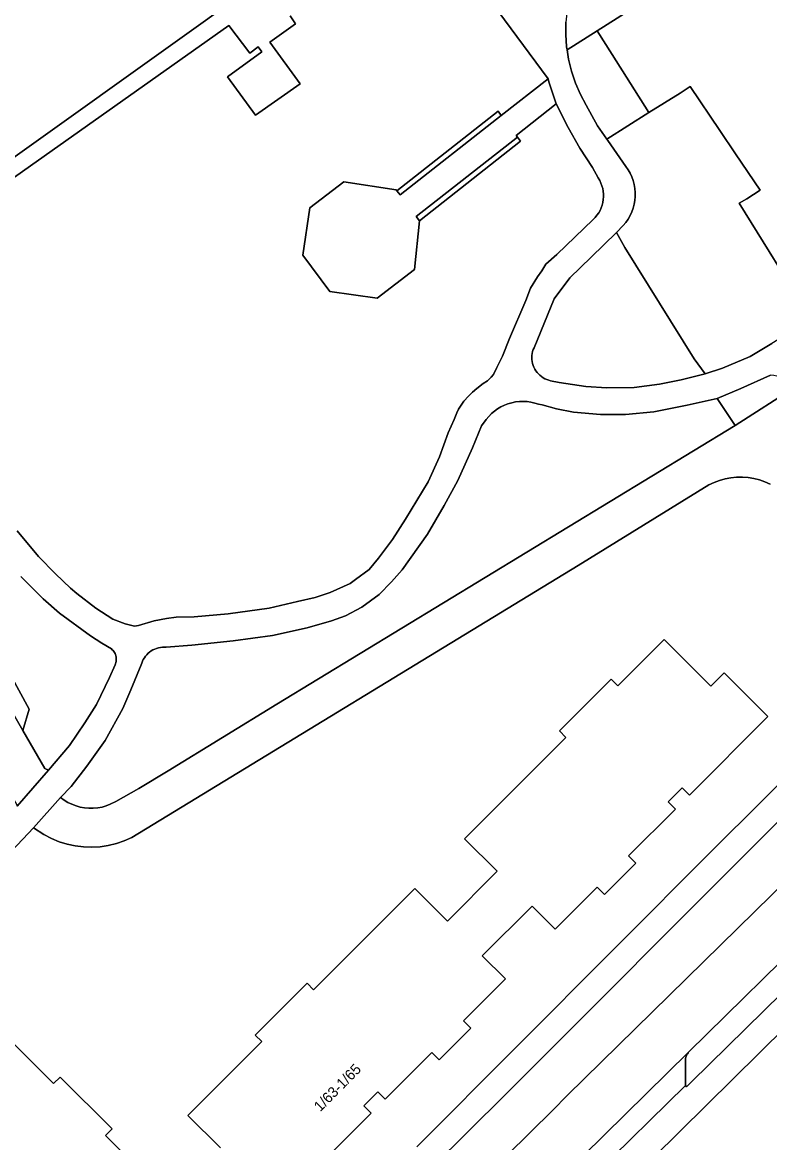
# Model space of a CAD drawing. Extents: x 162788 to 163838, y 385791 to 386523.
# Drawn here: x 163072 to 163143.1, y 386105.3 to 386211.9 of the extents above; entities that cross this region are included whole.
import ezdxf

# ---------------------------------------------------------------- set-up
doc = ezdxf.new("R2010")
doc.units = 0
for name, color, linetype in [('IMGEO_Berm_groen', 7, 'Continuous'), ('IMGEO_Erf', 7, 'Continuous'), ('IMGEO_Groenvoorziening', 7, 'Continuous'), ('IMGEO_Pand', 7, 'Continuous'), ('IMGEO_Pand_nummerreeks', 7, 'Continuous'), ('IMGEO_Parkeervlak_open', 7, 'Continuous'), ('IMGEO_Voetpad_open', 7, 'Continuous'), ('IMGEO_Woonerf_gesloten', 7, 'Continuous'), ('IMGEO_Woonerf_open', 7, 'Continuous')]:
    doc.layers.add(name, color=color, linetype=linetype)

msp = doc.modelspace()

# ---------------------------------------------------------------- linework, layer by layer
at = {"layer": 'IMGEO_Berm_groen'}
for points in [[(163156.62, 386148.64), (163142.94, 386134.85), (163117.96, 386109.83), (163097.04, 386089.07)], [(163102.96, 386089.09), (163122.49, 386108.37), (163123.87, 386109.74), (163156.29, 386141.59)], [(163160.09, 386138.11), (163135.42, 386113.88), (163135.36, 386113.81), (163135.3, 386113.73), (163135.25, 386113.65), (163135.21, 386113.57), (163135.17, 386113.48), (163135.14, 386113.39), (163135.12, 386113.29), (163135.12, 386110.69), (163135.22, 386110.58), (163135.7, 386111.04), (163166.6, 386141.42)]]:
    msp.add_lwpolyline(points, dxfattribs=at)
at = {"layer": 'IMGEO_Erf'}
msp.add_lwpolyline([(163158.27, 386231.02), (163155.82, 386235.03), (163136.27, 386225.97), (163132.74, 386224.35), (163130.49, 386223.11), (163129.8, 386222.6), (163128.43, 386221.27), (163127.43, 386220.24), (163126.53, 386219.13), (163125.72, 386217.95), (163125.01, 386216.7), (163124.41, 386215.4), (163124.09, 386214.26), (163123.87, 386213.1), (163123.75, 386211.92), (163123.73, 386210.74), (163123.81, 386209.56), (163123.86, 386209.28), (163126.72, 386211.09), (163130.88, 386213.71)], close=True, dxfattribs=at)
for points in [[(163053.39, 386193.12), (163054.82, 386191.67), (163058.03, 386187.75), (163058.05, 386187.72), (163059.18, 386188.5), (163060.22, 386187.16), (163063.6, 386189.54), (163061.56, 386192.21), (163063.86, 386193.8), (163094.9, 386216.01), (163096.44, 386213.92), (163109.74, 386223.18)], [(163143.18, 386167.94), (163142.67, 386168.17), (163142.15, 386168.35), (163141.62, 386168.49), (163141.08, 386168.58), (163140.53, 386168.61), (163139.98, 386168.61), (163139.43, 386168.55), (163138.89, 386168.45), (163138.36, 386168.29), (163137.85, 386168.1), (163137.35, 386167.86), (163124.9, 386160.21), (163082.45, 386134.32), (163081.73, 386133.99), (163080.98, 386133.73), (163080.21, 386133.55), (163079.42, 386133.43), (163078.63, 386133.38), (163077.84, 386133.41), (163077.05, 386133.5), (163076.28, 386133.67), (163075.52, 386133.91), (163074.79, 386134.21), (163074.09, 386134.58), (163073.09, 386135.24), (163062.74, 386124.27)], [(163090.89, 386104.76), (163087.79, 386107.86), (163094.81, 386114.88), (163094.19, 386115.5), (163099.12, 386120.43), (163099.74, 386119.81), (163109.38, 386129.45), (163112.48, 386126.35), (163117.21, 386131.09), (163114.11, 386134.18), (163123.75, 386143.82), (163123.13, 386144.45), (163128.06, 386149.38), (163128.68, 386148.76), (163133.09, 386153.16), (163137.54, 386148.71), (163138.81, 386149.98), (163142.96, 386145.82), (163135.49, 386138.35), (163134.8, 386139.04), (163133.47, 386137.71), (163134.16, 386137.02), (163129.71, 386132.57), (163130.41, 386131.87), (163127.41, 386128.87), (163126.71, 386129.57), (163122.72, 386125.58), (163120.52, 386127.78), (163115.79, 386123.04), (163117.99, 386120.85), (163114, 386116.86), (163114.7, 386116.16), (163111.7, 386113.16), (163111, 386113.85), (163106.55, 386109.4), (163105.86, 386110.09), (163104.53, 386108.77), (163105.22, 386108.08), (163097.75, 386100.6)], [(163109.57, 386104.88), (163137.82, 386133.23), (163155.34, 386150.64)], [(163144.69, 386116.33), (163116.89, 386088.83), (163094.14, 386066.38), (163090.23, 386062.55), (163093.08, 386059.67), (163106.35, 386045.61), (163117.91, 386034.05), (163120.62, 386031.36)], [(163068.21, 386100.47), (163060.74, 386107.94), (163064.89, 386112.09), (163066.15, 386110.83), (163070.61, 386115.28), (163075.01, 386110.88), (163075.64, 386111.5), (163080.57, 386106.57), (163079.95, 386105.95), (163086.01, 386099.88)]]:
    msp.add_lwpolyline(points, dxfattribs=at)
at = {"layer": 'IMGEO_Groenvoorziening'}
for points in [[(163071.54, 386163.51), (163073.56, 386161.05), (163075.18, 386159.4), (163076.62, 386158.04), (163077.2, 386157.52), (163079.02, 386156.14), (163080.64, 386155.08), (163081.8, 386154.63), (163082.69, 386154.41), (163083.07, 386154.49), (163084.57, 386154.93), (163085.75, 386155.14), (163086.66, 386155.28), (163088.39, 386155.32), (163091.61, 386155.59), (163095.5, 386156.15), (163098.2, 386156.77), (163099.9, 386157.14), (163101.31, 386157.62), (163103.23, 386158.49), (163103.72, 386158.86), (163105.02, 386159.82), (163105.9, 386160.88), (163107.26, 386162.67), (163108.48, 386164.62), (163110.65, 386168.17), (163111.72, 386170.55), (163112.54, 386172.83), (163113.11, 386174.1), (163113.35, 386174.73), (163113.54, 386175.09), (163113.84, 386175.55), (163114.02, 386175.85), (163114.47, 386176.33), (163114.86, 386176.7), (163115.28, 386177.04), (163115.87, 386177.51), (163116.29, 386177.79), (163116.62, 386178.12), (163116.85, 386178.38), (163117.16, 386179.04), (163117.72, 386180.13), (163118.37, 386181.8), (163119.94, 386185.43), (163120.38, 386186.59), (163121.05, 386187.67), (163121.44, 386188.25), (163121.84, 386188.88), (163122.87, 386189.8), (163126.34, 386193.13), (163126.53, 386193.32), (163126.7, 386193.53), (163126.86, 386193.75), (163126.99, 386193.99), (163127.1, 386194.23), (163127.19, 386194.49), (163127.26, 386194.75), (163127.3, 386195.02), (163127.33, 386195.28), (163127.32, 386195.55), (163127.3, 386195.82), (163127.25, 386196.09), (163127.17, 386196.35), (163127.08, 386196.6), (163126.96, 386196.84), (163126.82, 386197.08), (163126.26, 386198.09), (163125.07, 386199.91), (163123.96, 386201.89), (163122.83, 386204.14), (163119.02, 386201.14), (163119.14, 386200.98), (163119.42, 386200.57), (163109.81, 386193.01), (163109.35, 386188.38), (163105.8, 386185.63), (163101.28, 386186.28), (163098.72, 386189.72), (163099.37, 386194.23), (163102.62, 386196.71), (163107.59, 386195.96), (163107.67, 386195.86), (163117.29, 386203.43), (163117.59, 386203.03), (163122.04, 386206.53), (163110.75, 386221.82)], [(163097.5, 386212.51), (163098.02, 386211.76), (163095.56, 386210), (163098.45, 386206.04), (163094.22, 386203.06), (163091.55, 386206.71), (163094.83, 386209.1), (163094.46, 386209.55), (163093.67, 386208.95), (163091.66, 386211.58), (163067.36, 386194.4)], [(163065.54, 386159.58), (163072.69, 386146.51), (163072.09, 386144.5), (163074.17, 386140.87), (163074.53, 386140.72), (163076.51, 386143.08), (163077.98, 386145.21), (163079.09, 386146.97), (163080.31, 386149.54), (163080.85, 386150.74), (163080.89, 386150.84), (163080.93, 386150.95), (163080.95, 386151.06), (163080.96, 386151.17), (163080.97, 386151.28), (163080.96, 386151.39), (163080.95, 386151.5), (163080.92, 386151.61), (163080.89, 386151.72), (163080.85, 386151.82), (163080.8, 386151.92), (163080.74, 386152.01), (163080.67, 386152.1), (163080.59, 386152.18), (163080.51, 386152.26), (163079.58, 386152.81), (163078.51, 386153.5), (163075.55, 386155.66), (163074.02, 386157.02), (163071.9, 386159.16)]]:
    msp.add_lwpolyline(points, dxfattribs=at)
for points in [[(163128.15, 386208.82), (163126.72, 386211.09), (163123.86, 386209.28), (163123.99, 386208.39), (163124.27, 386207.24), (163124.65, 386206.12), (163125.12, 386205.04), (163125.68, 386204), (163126.76, 386202.06), (163127.64, 386200.78), (163131.63, 386203.3)], [(163117.59, 386203.03), (163117.29, 386203.43), (163107.67, 386195.86), (163107.98, 386195.47)], [(163119.14, 386200.98), (163109.51, 386193.41), (163109.81, 386193.01), (163119.42, 386200.57)], [(163128.55, 386191.88), (163126.16, 386189.53), (163124.11, 386187.59), (163122.62, 386185.59), (163120.71, 386180.93), (163120.63, 386180.75), (163120.58, 386180.57), (163120.53, 386180.38), (163120.51, 386180.19), (163120.5, 386179.99), (163120.51, 386179.8), (163120.53, 386179.61), (163120.57, 386179.42), (163120.63, 386179.24), (163120.7, 386179.06), (163120.79, 386178.89), (163120.89, 386178.73), (163121, 386178.57), (163121.13, 386178.43), (163121.27, 386178.3), (163121.42, 386178.18), (163121.58, 386178.07), (163121.75, 386177.98), (163121.93, 386177.9), (163122.11, 386177.84), (163122.29, 386177.79), (163123.1, 386177.61), (163125.63, 386177.23), (163127.65, 386177.12), (163130.25, 386177.15), (163132.65, 386177.47), (163134.71, 386177.86), (163137, 386178.43), (163135.96, 386179.87), (163129.36, 386190.45)], [(163139.83, 386173.53), (163138.14, 386176.08), (163135.28, 386175.46), (163132.12, 386174.82), (163129.41, 386174.56), (163127.04, 386174.57), (163124.47, 386174.8), (163122.86, 386175.11), (163121.47, 386175.48), (163121.13, 386175.55), (163120.78, 386175.66), (163120.42, 386175.74), (163120.05, 386175.8), (163119.68, 386175.82), (163119.32, 386175.81), (163118.95, 386175.77), (163118.59, 386175.69), (163118.23, 386175.59), (163117.89, 386175.46), (163117.56, 386175.29), (163117.24, 386175.1), (163116.94, 386174.89), (163116.66, 386174.65), (163116.41, 386174.38), (163116.17, 386174.1), (163115.72, 386173.49), (163114.87, 386171.39), (163113.47, 386168.28), (163112.16, 386165.91), (163110.57, 386163.17), (163108.16, 386159.77), (163107.15, 386158.64), (163105.97, 386157.44), (163104.33, 386156.22), (163102.78, 386155.42), (163101.45, 386154.94), (163099.12, 386154.28), (163095.84, 386153.54), (163092.09, 386153.03), (163088.17, 386152.63), (163085.72, 386152.41), (163085.54, 386152.42), (163085.35, 386152.42), (163085.16, 386152.4), (163084.98, 386152.36), (163084.8, 386152.31), (163084.62, 386152.24), (163084.46, 386152.16), (163084.29, 386152.07), (163084.14, 386151.96), (163084, 386151.84), (163083.87, 386151.71), (163083.75, 386151.57), (163083.64, 386151.41), (163083.54, 386151.25), (163083.46, 386151.08), (163083.4, 386150.91), (163083.35, 386150.73), (163082.34, 386148.35), (163081.58, 386146.58), (163079.91, 386143.55), (163078.18, 386141.11), (163076.67, 386139.15), (163075.67, 386138.11), (163076.01, 386137.86), (163076.37, 386137.65), (163076.74, 386137.47), (163077.14, 386137.32), (163077.54, 386137.21), (163077.95, 386137.14), (163078.36, 386137.1), (163078.78, 386137.1), (163079.2, 386137.14), (163079.61, 386137.21), (163080.01, 386137.32), (163080.4, 386137.47), (163080.93, 386137.74), (163083.12, 386138.98), (163085.91, 386140.64), (163096.25, 386147)]]:
    msp.add_lwpolyline(points, close=True, dxfattribs=at)
at = {"layer": 'IMGEO_Pand'}
for points in [[(163158.27, 386231.02), (163130.88, 386213.71), (163126.72, 386211.09), (163128.15, 386208.82), (163131.63, 386203.3), (163134.6, 386205.17), (163135.58, 386205.79), (163138.39, 386201.6), (163139.88, 386199.39), (163142.21, 386195.91), (163140.94, 386195.11), (163140.23, 386194.67), (163146.92, 386183.91)], [(163097.75, 386100.6), (163105.22, 386108.08), (163104.53, 386108.77), (163105.86, 386110.09), (163106.55, 386109.4), (163111, 386113.85), (163111.7, 386113.16), (163114.7, 386116.16), (163114, 386116.86), (163117.99, 386120.85), (163115.79, 386123.04), (163120.52, 386127.78), (163122.72, 386125.58), (163126.71, 386129.57), (163127.41, 386128.87), (163130.41, 386131.87), (163129.71, 386132.57), (163134.16, 386137.02), (163133.47, 386137.71), (163134.8, 386139.04), (163135.49, 386138.35), (163142.96, 386145.82), (163138.81, 386149.98), (163137.54, 386148.71), (163133.09, 386153.16), (163128.68, 386148.76), (163128.06, 386149.38), (163123.13, 386144.45), (163123.75, 386143.82), (163114.11, 386134.18), (163117.21, 386131.09), (163112.48, 386126.35), (163109.38, 386129.45), (163099.74, 386119.81), (163099.12, 386120.43), (163094.19, 386115.5), (163094.81, 386114.88), (163087.79, 386107.86), (163090.89, 386104.76)], [(163086.01, 386099.88), (163079.95, 386105.95), (163080.57, 386106.57), (163075.64, 386111.5), (163075.01, 386110.88), (163070.61, 386115.28), (163066.15, 386110.83), (163064.89, 386112.09), (163060.74, 386107.94), (163068.21, 386100.47)]]:
    msp.add_lwpolyline(points, dxfattribs=at)
at = {"layer": 'IMGEO_Parkeervlak_open'}
for points in [[(163063.12, 386160.14), (163072.09, 386144.5), (163072.69, 386146.51), (163065.54, 386159.58)], [(163135.12, 386110.69), (163135.12, 386113.29), (163135.14, 386113.39), (163135.17, 386113.48), (163135.21, 386113.57), (163135.25, 386113.65), (163135.3, 386113.73), (163135.36, 386113.81), (163135.42, 386113.88), (163123.39, 386102.04), (163123.47, 386102.09), (163123.55, 386102.13), (163123.63, 386102.16), (163123.71, 386102.19), (163123.8, 386102.2), (163123.89, 386102.21), (163123.98, 386102.21), (163126.52, 386102.25)]]:
    msp.add_lwpolyline(points, close=True, dxfattribs=at)
at = {"layer": 'IMGEO_Voetpad_open'}
for points in [[(163094.9, 386216.01), (163063.86, 386193.8), (163061.56, 386192.21), (163063.6, 386189.54), (163060.22, 386187.16), (163059.18, 386188.5), (163058.05, 386187.72), (163059, 386186.38), (163059.81, 386184.94), (163066.76, 386190), (163064.81, 386192.51), (163067.36, 386194.4), (163091.66, 386211.58), (163093.67, 386208.95), (163094.46, 386209.55), (163094.83, 386209.1), (163091.55, 386206.71), (163094.22, 386203.06), (163098.45, 386206.04), (163095.56, 386210), (163098.02, 386211.76), (163097.5, 386212.51)], [(163146.92, 386183.91), (163140.23, 386194.67), (163140.94, 386195.11), (163142.21, 386195.91), (163139.88, 386199.39), (163138.39, 386201.6), (163135.58, 386205.79), (163134.6, 386205.17), (163131.63, 386203.3), (163127.64, 386200.78), (163127.74, 386200.64), (163129.44, 386198.18), (163129.66, 386197.87), (163129.85, 386197.54), (163130.01, 386197.2), (163130.14, 386196.84), (163130.24, 386196.47), (163130.3, 386196.09), (163130.33, 386195.71), (163130.33, 386195.33), (163130.3, 386194.95), (163130.24, 386194.58), (163130.14, 386194.21), (163130.01, 386193.85), (163129.85, 386193.51), (163129.65, 386193.17), (163129.43, 386192.86), (163129.19, 386192.57), (163128.55, 386191.88), (163129.36, 386190.45), (163135.96, 386179.87), (163137, 386178.43), (163138.64, 386178.99), (163141.28, 386180.1), (163143.33, 386181.33)]]:
    msp.add_lwpolyline(points, dxfattribs=at)
msp.add_lwpolyline([(163119.14, 386200.98), (163119.02, 386201.14), (163122.83, 386204.14), (163122.15, 386206.14), (163122.12, 386206.23), (163122.04, 386206.53), (163117.59, 386203.03), (163107.98, 386195.47), (163107.67, 386195.86), (163107.59, 386195.96), (163102.62, 386196.71), (163099.37, 386194.23), (163098.72, 386189.72), (163101.28, 386186.28), (163105.8, 386185.63), (163109.35, 386188.38), (163109.81, 386193.01), (163109.51, 386193.41)], close=True, dxfattribs=at)
at = {"layer": 'IMGEO_Woonerf_gesloten'}
for points in [[(163110.75, 386221.82), (163122.04, 386206.53), (163122.12, 386206.23), (163122.15, 386206.14), (163122.83, 386204.14), (163123.96, 386201.89), (163125.07, 386199.91), (163126.26, 386198.09), (163126.82, 386197.08), (163126.96, 386196.84), (163127.08, 386196.6), (163127.17, 386196.35), (163127.25, 386196.09), (163127.3, 386195.82), (163127.32, 386195.55), (163127.33, 386195.28), (163127.3, 386195.02), (163127.26, 386194.75), (163127.19, 386194.49), (163127.1, 386194.23), (163126.99, 386193.99), (163126.86, 386193.75), (163126.7, 386193.53), (163126.53, 386193.32), (163126.34, 386193.13), (163122.87, 386189.8), (163121.84, 386188.88), (163121.44, 386188.25), (163121.05, 386187.67), (163120.38, 386186.59), (163119.94, 386185.43), (163118.37, 386181.8), (163117.72, 386180.13), (163117.16, 386179.04), (163116.85, 386178.38), (163116.62, 386178.12), (163116.29, 386177.79), (163115.87, 386177.51), (163115.28, 386177.04), (163114.86, 386176.7), (163114.47, 386176.33), (163114.02, 386175.85), (163113.84, 386175.55), (163113.54, 386175.09), (163113.35, 386174.73), (163113.11, 386174.1), (163112.54, 386172.83), (163111.72, 386170.55), (163110.65, 386168.17), (163108.48, 386164.62), (163107.26, 386162.67), (163105.9, 386160.88), (163105.02, 386159.82), (163103.72, 386158.86), (163103.23, 386158.49), (163101.31, 386157.62), (163099.9, 386157.14), (163098.2, 386156.77), (163095.5, 386156.15), (163091.61, 386155.59), (163088.39, 386155.32), (163086.66, 386155.28), (163085.75, 386155.14), (163084.57, 386154.93), (163083.07, 386154.49), (163082.69, 386154.41), (163081.8, 386154.63), (163080.64, 386155.08), (163079.02, 386156.14), (163077.2, 386157.52), (163076.62, 386158.04), (163075.18, 386159.4), (163073.56, 386161.05), (163071.54, 386163.51)], [(163122.29, 386177.79), (163122.11, 386177.84), (163121.93, 386177.9), (163121.75, 386177.98), (163121.58, 386178.07), (163121.42, 386178.18), (163121.27, 386178.3), (163121.13, 386178.43), (163121, 386178.57), (163120.89, 386178.73), (163120.79, 386178.89), (163120.7, 386179.06), (163120.63, 386179.24), (163120.57, 386179.42), (163120.53, 386179.61), (163120.51, 386179.8), (163120.5, 386179.99), (163120.51, 386180.19), (163120.53, 386180.38), (163120.58, 386180.57), (163120.63, 386180.75), (163120.71, 386180.93), (163122.62, 386185.59), (163124.11, 386187.59), (163126.16, 386189.53), (163128.55, 386191.88), (163129.19, 386192.57), (163129.43, 386192.86), (163129.65, 386193.17), (163129.85, 386193.51), (163130.01, 386193.85), (163130.14, 386194.21), (163130.24, 386194.58), (163130.3, 386194.95), (163130.33, 386195.33), (163130.33, 386195.71), (163130.3, 386196.09), (163130.24, 386196.47), (163130.14, 386196.84), (163130.01, 386197.2), (163129.85, 386197.54), (163129.66, 386197.87), (163129.44, 386198.18), (163127.74, 386200.64), (163127.64, 386200.78), (163126.76, 386202.06), (163125.68, 386204), (163125.12, 386205.04), (163124.65, 386206.12), (163124.27, 386207.24), (163123.99, 386208.39), (163123.86, 386209.28), (163123.81, 386209.56), (163123.73, 386210.74), (163123.75, 386211.92)], [(163178.31, 386198.47), (163176.71, 386201.87), (163165.46, 386195.06), (163147, 386183.52), (163144.74, 386182.18), (163143.33, 386181.33), (163141.28, 386180.1), (163138.64, 386178.99), (163137, 386178.43), (163134.71, 386177.86), (163132.65, 386177.47), (163130.25, 386177.15), (163127.65, 386177.12), (163125.63, 386177.23), (163123.1, 386177.61), (163122.29, 386177.79)], [(163062.74, 386124.27), (163073.09, 386135.24), (163075.67, 386138.11), (163076.67, 386139.15), (163078.18, 386141.11), (163079.91, 386143.55), (163081.58, 386146.58), (163082.34, 386148.35), (163083.35, 386150.73), (163083.4, 386150.91), (163083.46, 386151.08), (163083.54, 386151.25), (163083.64, 386151.41), (163083.75, 386151.57), (163083.87, 386151.71), (163084, 386151.84), (163084.14, 386151.96), (163084.29, 386152.07), (163084.46, 386152.16), (163084.62, 386152.24), (163084.8, 386152.31), (163084.98, 386152.36), (163085.16, 386152.4), (163085.35, 386152.42), (163085.54, 386152.42), (163085.72, 386152.41), (163088.17, 386152.63), (163092.09, 386153.03), (163095.84, 386153.54), (163099.12, 386154.28), (163101.45, 386154.94), (163102.78, 386155.42), (163104.33, 386156.22), (163105.97, 386157.44), (163107.15, 386158.64), (163108.16, 386159.77), (163110.57, 386163.17), (163112.16, 386165.91), (163113.47, 386168.28), (163114.87, 386171.39), (163115.72, 386173.49), (163116.17, 386174.1), (163116.41, 386174.38), (163116.66, 386174.65), (163116.94, 386174.89), (163117.24, 386175.1), (163117.56, 386175.29), (163117.89, 386175.46), (163118.23, 386175.59), (163118.59, 386175.69), (163118.95, 386175.77), (163119.32, 386175.81), (163119.68, 386175.82), (163120.05, 386175.8), (163120.42, 386175.74), (163120.78, 386175.66), (163121.13, 386175.55), (163121.47, 386175.48), (163122.86, 386175.11), (163124.47, 386174.8), (163127.04, 386174.57), (163129.41, 386174.56), (163132.12, 386174.82), (163135.28, 386175.46), (163138.14, 386176.08), (163140.39, 386177.04), (163143.2, 386178.32)], [(163071.9, 386159.16), (163074.02, 386157.02), (163075.55, 386155.66), (163078.51, 386153.5), (163079.58, 386152.81), (163080.51, 386152.26), (163080.59, 386152.18), (163080.67, 386152.1), (163080.74, 386152.01), (163080.8, 386151.92), (163080.85, 386151.82), (163080.89, 386151.72), (163080.92, 386151.61), (163080.95, 386151.5), (163080.96, 386151.39), (163080.97, 386151.28), (163080.96, 386151.17), (163080.95, 386151.06), (163080.93, 386150.95), (163080.89, 386150.84), (163080.85, 386150.74), (163080.31, 386149.54), (163079.09, 386146.97), (163077.98, 386145.21), (163076.51, 386143.08), (163074.53, 386140.72), (163071.55, 386137.29)], [(163155.34, 386150.64), (163137.82, 386133.23), (163109.57, 386104.88)], [(163097.04, 386089.07), (163117.96, 386109.83), (163142.94, 386134.85), (163156.62, 386148.64)], [(163166.6, 386141.42), (163135.7, 386111.04), (163135.22, 386110.58), (163135.12, 386110.69), (163126.52, 386102.25)], [(163116.89, 386088.83), (163144.69, 386116.33)]]:
    msp.add_lwpolyline(points, dxfattribs=at)
at = {"layer": 'IMGEO_Woonerf_open'}
for points in [[(163145.58, 386177.19), (163145.4, 386177.37), (163145.17, 386177.57), (163144.92, 386177.74), (163144.66, 386177.9), (163144.39, 386178.04), (163144.1, 386178.15), (163143.8, 386178.23), (163143.51, 386178.29), (163143.2, 386178.32), (163140.39, 386177.04), (163138.14, 386176.08), (163139.83, 386173.53)], [(163063.12, 386160.14), (163054.33, 386175.48), (163050.86, 386173.7), (163071.46, 386137.47), (163071.55, 386137.29), (163074.53, 386140.72), (163074.17, 386140.87), (163072.09, 386144.5)]]:
    msp.add_lwpolyline(points, close=True, dxfattribs=at)
for points in [[(163145.58, 386177.19), (163139.83, 386173.53), (163096.25, 386147), (163085.91, 386140.64), (163083.12, 386138.98), (163080.93, 386137.74), (163080.4, 386137.47), (163080.01, 386137.32), (163079.61, 386137.21), (163079.2, 386137.14), (163078.78, 386137.1), (163078.36, 386137.1), (163077.95, 386137.14), (163077.54, 386137.21), (163077.14, 386137.32), (163076.74, 386137.47), (163076.37, 386137.65), (163076.01, 386137.86), (163075.67, 386138.11), (163073.09, 386135.24), (163074.09, 386134.58), (163074.79, 386134.21), (163075.52, 386133.91), (163076.28, 386133.67), (163077.05, 386133.5), (163077.84, 386133.41), (163078.63, 386133.38), (163079.42, 386133.43), (163080.21, 386133.55), (163080.98, 386133.73), (163081.73, 386133.99), (163082.45, 386134.32), (163124.9, 386160.21), (163137.35, 386167.86), (163137.85, 386168.1), (163138.36, 386168.29), (163138.89, 386168.45), (163139.43, 386168.55), (163139.98, 386168.61), (163140.53, 386168.61), (163141.08, 386168.58), (163141.62, 386168.49), (163142.15, 386168.35), (163142.67, 386168.17), (163143.18, 386167.94)], [(163156.29, 386141.59), (163123.87, 386109.74), (163122.49, 386108.37), (163102.96, 386089.09)], [(163123.39, 386102.04), (163135.42, 386113.88), (163160.09, 386138.11)]]:
    msp.add_lwpolyline(points, dxfattribs=at)

# ---------------------------------------------------------------- texts
at = {"layer": 'IMGEO_Pand_nummerreeks'}
msp.add_text('1/63-1/65', height=1, rotation=45.2846, dxfattribs=at).set_placement((163100.37, 386108.15))

doc.saveas('drawing.dxf')
